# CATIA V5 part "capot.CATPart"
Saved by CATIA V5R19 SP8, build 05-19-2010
Part number: capot
Bounding box of the stored display mesh (mm): x 135.383 to 238.883, y -132.49 to 132.49, z -132.385 to 132.385
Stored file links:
  U:\Rendu_cfao_elguidj\capot.CATPart
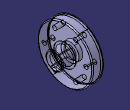
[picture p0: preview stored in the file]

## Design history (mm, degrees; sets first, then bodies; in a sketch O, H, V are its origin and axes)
Body1 (main body)
  DatumCurve1
  DatumSurface1
  DatumCurve2
  DatumCurve3
  DatumSurface2
  DatumSurface3
  DatumCurve4
  DatumCurve5
  DatumSurface4 to DatumSurface6
  DatumCurve6
  DatumCurve7
  DatumSurface7
  DatumCurve8
  Sketch1 on zx-plane, origin (0, 0, 0), H (-1, 0, 0), V (0, 0, 1)
    line L1 (-135.3829, 128.5) -> (-135.3829, 132.5)
    line L2 (-135.3829, 132.5) -> (-181.8829, 132.5)
    point P3 (-181.8829, 132.5)
    line L3 (-181.8829, 132.5) -> (-186.8829, 127.5)
    line L4 (-186.8829, 127.5) -> (-186.8829, 52.5)
    line L5 (-186.8829, 52.5) -> (-188.8829, 52.5)
    line L6 (-188.8829, 52.5) -> (-188.8829, 42.5)
    line L7 (-188.8829, 42.5) -> (-235.8829, 42.5)
    point P8 (-235.8829, 42.5)
    line L8 (-235.8829, 42.5) -> (-238.8829, 37.3038)
    point P9 (-238.8829, 37.3038)
    line L9 (-238.8829, 37.3038) -> (-230.5791, 29)
    line L10 (-230.5791, 29) -> (-163.117, 29)
    line L11 (-163.117, 29) -> (-163.117, 42.5)
    line L12 (-163.117, 42.5) -> (-144.3829, 42.5)
    line L13 (-144.3829, 42.5) -> (-144.3829, 128.5)
    line L14 (-144.3829, 128.5) -> (-135.3829, 128.5)
    reference projected line E1 (-412.703, 0) -> (326.9047, 0) from edge of DatumCurve3
    reference intersected line E2 through (-163.117, 0) direction (0, 1) from face of DatumSurface2
    reference projected line E3 (-412.703, 0) -> (326.9047, 0) from edge of DatumCurve5
    reference intersected line E4 through (-144.3829, 0) direction (0, -1) from face of DatumSurface4
    reference projected line E5 (-412.703, 0) -> (326.9047, 0) from edge of DatumCurve6
    construction line L15 (-235.8829, 19.7244) -> (-235.8829, 56.0684)
    reference projected line E6 (-412.703, 0) -> (326.9047, 0) from edge of DatumCurve7
    reference intersected line E7 through (-134.3829, 0) direction (0, -1) from face of DatumSurface7
    axis line L16 (-181.8829, 145.5002) -> (-181.8829, 112.4058)
    distance L12 E1 = 42.5
    distance L10 E3 = 29
    angle L9 L10 = 45
    angle L8 L7 = 60
    distance L6 P9 = 50
    distance L13 L4 = 42.5
    distance L6 L4 = 2
    distance L5 E5 = 52.5
    distance P9 L15 = 3
    distance L14 E6 = 128.5
    angle L3 L2 = 45
    distance L14 L2 = 4
    distance L1 E7 = 1
    distance L4 L16 = 5
    vertical: L1 V, L4 V, L6 V, L11 V, L13 V, L15 V, L16 V
    horizontal: L2 H, L5 H, L7 H, L10 H, L12 H, L14 H
    coincidence: L11 E2, L7 L12, L13 E4, L15 P8, L16 P3
  Shaft1: profile Sketch1, axis edge of DatumCurve8, angle 360
  Sketch2 on face of Shaft1 from Sketch1.L4, origin (186.8829, -47.171, 84.516), H (0, 1, 0), V (0, 0, 1)
    point P1 (-2.829, 2.0865)
    axis line L1 (154.6578, -270.6887) -> (-62.3217, 105.1309)
    reference projected point E1 (47.171, -84.516) from vertex of DatumPoint1
    reference projected point E2 (47.171, -84.516) from vertex of DatumPoint2
    angle L1 V = 30
    distance E2 P1 = 100
    coincidence: L1 E1, P1 L1
  Hole1: placed by Sketch2, at (186.8829, -50, 86.6025) direction (-1, 0, 0), diameter 20, through (limit type 6)
  DatumCurve9
  CircPattern1: of Hole1, instances 6, angular step 60, axis from edge of DatumCurve9
  DatumPoint1
  DatumPoint2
